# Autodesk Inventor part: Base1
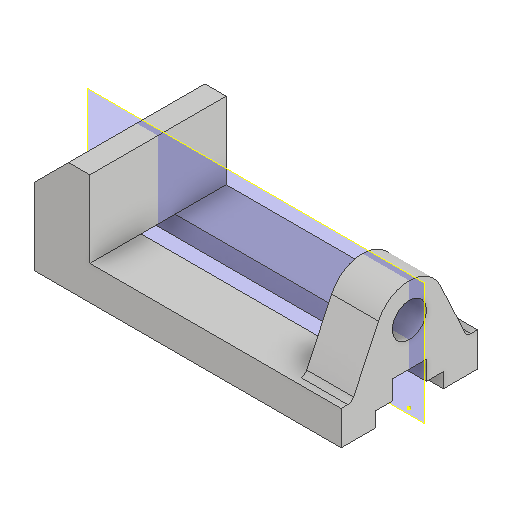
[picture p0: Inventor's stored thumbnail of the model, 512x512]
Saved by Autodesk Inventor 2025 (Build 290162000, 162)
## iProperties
Created: 2016-03
Part Number: Base1
Material: Generic
Document SubType Name: Modeling
Designer: Sandeep
Density: 1 g/cm^3
Appearance: Default
Author: Sandeep
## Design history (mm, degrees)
sketch "Sketch1"
  geometry: L1 (0, 0)-(0, 16); L2 (0, 16)-(118, 16); L3 (118, 16)-(118, 52); L4 (118, 52)-(144, 52); L5 (144, 52)-(144, 0); L6 (144, 0)-(0, 0)
  constraints: 12 end point, 3 perpendicular, 1 vertical
  dimensions: "d1" = 144 distance of L5.end L1.start; "d2" = 26 distance of L3.end L4.end; "d3" = 16 distance between parallel lines of L6 L2; "d4" = 36 distance between parallel lines of L2 L4
extrude "Extrusion1" new body sketch "Sketch1" stored distance "d5" = 64; taper "d6" = 0 deg
chamfer "Chamfer1" distance "d7" = 16; stored, may be unused: second distance "d8" = 16, angle "d9" = 45 deg
sketch "Sketch5"
  geometry: L1 (-16, 5.02)-(-42.762, 17.499); L2 (-42.762, 46.501)-(-16, 58.98); L3 (-52, 64)-(-52, 0) reference; L4 (-16, 32)-(-54.774, 32); L5 (-52, 64)-(-16, 64) reference; L6 (-16, 64)-(-16, 0) reference; L7 (-16, 5.02)-(-16, 58.98); L8 (0, 64)-(0, 0) reference; A1 r 16 centre (-36, 32) between (-42.762, 46.501) and (-42.762, 17.499); 1 further point
  constraints: 8 end point, 3 point on line, 3 tangent, 2 point on circle, 1 centre point, 1 collinear, 1 horizontal, 1 other
  dimensions: "d21" = 50 deg angle of L2 L1; "d22" = 36 distance from line of L8 A1.centre
extrude "Extrusion2" join sketch "Sketch5" distance "d23" = 22; taper "d24" = 0 deg
fillet "Fillet1" dims "d25" = 3
sketch "Sketch6"
  geometry: L1 (-36, 64)-(-36, 0) reference; C1 r 8 at (-36, 32); A1 r 16 centre (-36, 32) between (-42.762, 46.501) and (-42.762, 17.499) reference; 1 further point
  constraints: 1 centre point, 1 concentric, 1 midpoint
  dimensions: "d26" = 16 diameter of C1
extrude "Extrusion3" cut sketch "Sketch6" distance "d27" = 22; taper "d28" = 0 deg
sketch "Sketch7"
  geometry: L1 (0, 0)-(0, 64) reference; L2 (0, 16)-(-7, 16); L3 (-7, 16)-(-7, 24); L4 (-7, 24)-(-16, 24); L5 (-16, 3.109)-(-16, 60.891) reference; L6 (-16, 24)-(-16, 40); L7 (-7, 40)-(-7, 48); L8 (-7, 48)-(0, 48); L9 (0, 48)-(0, 16); L10 (-7, 40)-(-16, 40); L11 (-44, 32)-(-36, 32); 1 further point
  constraints: 18 end point, 6 point on line, 4 perpendicular, 2 horizontal, 1 collinear, 1 horizontal alignment, 4 other
  dimensions: "d29" = 32 distance between parallel lines of L2 L8; "d30" = 7 distance of L7.end L8.end; "d45" = 16 distance between parallel lines of L10 L4
extrude "Extrusion4" cut sketch "Sketch7" distance "d31" = 167.75; taper "d32" = 0 deg
sketch "Sketch8"
  geometry: L1 (144, 0)-(144, -16) reference; L2 (0, 0)-(144, 0) reference; L3 (0, -16)-(0, 0) reference; 3 further points
  dimensions: "d33" = 70 distance of point (108, -10) point (38, -10); "d35" = 10 distance from line of L2 point (108, -10); "d36" = 10 distance from line of L2 point (38, -10); "d46" = 38 distance from line of L3 point (38, -10)
hole "Hole1" sketch "Sketch8" diameter "d37" = 4.917; stored, may be unused: countersink angle "d41" = 90 deg, drill point angle "d43" = 118 deg; dims "d38" = 12, "d39" = 4, "d40" = 2, "d42" = 10
workplane "Work Plane1"
mirror "Mirror1"
body "Solid1"
sketch "Sketch4"
  geometry: 1 further point
other parameters: "d10" = 16, "d13" = 7, "d14" = 16, "d44" = -32
